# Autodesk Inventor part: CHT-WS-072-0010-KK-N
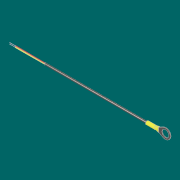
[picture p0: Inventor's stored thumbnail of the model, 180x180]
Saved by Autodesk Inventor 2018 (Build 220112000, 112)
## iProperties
Created: 2017-05
Part Number: CHT-WS-072-0010-KK-N
Material: Generic
Document SubType Name: Modeling
Designer: JN
Density: 1 g/cm^3
Appearance: Steel - Polished
Author: JN
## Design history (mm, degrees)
sketch "Sketch1"
  geometry: L1 (-3.534, 6.574)-(-10.033, 3.097); L2 (-10.033, 3.097)-(-10.033, -3.161); L3 (-10.033, -3.161)-(-3.425, -6.697); L4 (-10.033, -0.032)-(7.494, -0.032); L5 (0.001, 7.461)-(0.001, -7.525); C1 r 5.258 at (0.001, -0.032); A1 r 7.493 centre (0.001, -0.032) between (-3.534, -6.639) and (-3.534, 6.574)
  constraints: 10 end point, 5 point on circle, 2 centre point, 2 tangent, 2 vertical, 1 coincident, 1 midpoint, 1 point on line, 1 other
  dimensions: "d0" = 10.5156 diameter of C1; "d1" = 14.986 diameter of A1
extrude "Extrusion1" new body sketch "Sketch1" stored distance "d7" = 1.0668; taper "d8" = 0 deg
sketch "Sketch3"
  geometry: L1 (-1.067, 0)-(0, 0) reference; L2 (0, 6.258)-(0, 0) reference; L3 (-1.067, 6.258)-(0, 6.258) reference; L4 (-1.067, 0)-(-1.067, 6.258) reference; L5 (0.317, 6.575)-(-1.702, 6.575); L6 (-1.702, 6.575)-(-1.702, -0.318); L7 (-1.702, -0.318)-(0.317, -0.318); L8 (0.317, -0.318)-(0.317, 6.575); L9 (-0.692, 6.575)-(-0.692, -0.318); L10 (0.318, 3.129)-(-1.702, 3.129); 1 further point
  constraints: 12 end point, 6 parallel, 5 midpoint, 1 horizontal, 1 perpendicular
  dimensions: "d15" = 0.3175 distance between parallel lines of L2 L8; "d16" = 0.635 distance between parallel lines of L4 L6; "d17" = 0.3175 distance between parallel lines of L3 L5; "d18" = 0.3175 distance between parallel lines of L1 L7
  node "Projected Loop1"
workplane "Work Plane1"
sketch "Sketch4"
  geometry: L1 (0.317, -0.318)-(0.317, 6.575) reference; L2 (0.317, 6.575)-(-1.702, 6.575) reference; L3 (-1.702, 6.575)-(-1.702, -0.318) reference; L4 (-1.702, -0.318)-(0.317, -0.318) reference; L5 (0.317, 3.129)-(-1.702, 3.129); L6 (-0.692, 6.575)-(-0.692, -0.318); L7 (-2.337, 5.064)-(-2.337, 1.193); A1 r 2.54 centre (-0.692, 3.129) between (-2.337, 1.193) and (-2.337, 5.064); 2 further points
  constraints: 6 end point, 5 midpoint, 2 point on circle, 1 centre point, 1 coincident, 1 point on line, 1 vertical
  dimensions: "d37" = 5.08 diameter of A1; "d38" = 0.635 distance between parallel lines of L3 L7
sketch "3D Sketch1"
loft "Loft1" sketch "Sketch4", "3D Sketch1" dims "d21" = 0, "d22" = 90 deg, "d25" = 0, "d26" = 90 deg, "d39" = 0, "d40" = 90 deg
sketch "Sketch5"
  geometry: L1 (-0.635, 5.382)-(-0.635, 1.511) reference; A1 r 2.54 centre (1.01, 3.446) between (1.221, 0.915) and (1.928, 5.814) reference; A2 r 2.54 centre (1.01, 3.446) between (1.928, 5.814) and (-0.635, 5.382) reference; A3 r 2.54 centre (1.01, 3.446) between (1.928, 5.814) and (-0.635, 5.382) reference; A4 r 2.54 centre (1.01, 3.446) between (-0.635, 1.511) and (1.221, 0.915) reference; A5 r 2.54 centre (1.01, 3.446) between (1.221, 0.915) and (1.928, 5.814) reference
extrude "Extrusion3" new body sketch "Sketch5" distance "d27" = 12.7; taper "d28" = 0 deg
sketch "Sketch6" dims "d29" = 1.27, "d30" = 1.778
  geometry: L1 (2.019, 0)-(2.019, 6.893) reference; L2 (0, 6.893)-(0, 0) reference; L3 (2.019, 6.893)-(0, 6.893) reference; L4 (0, 0)-(2.019, 0) reference; L5 (2.019, 0)-(2.019, 6.893) reference; L6 (2.019, 6.893)-(0, 6.893) reference; L7 (1.01, 6.893)-(1.01, 0); L8 (0, 0)-(2.019, 0) reference; L9 (0, 6.893)-(0, 0) reference; L10 (0, 3.446)-(2.019, 3.446); 2 further points; 1 other entity
  constraints: 5 midpoint, 4 end point, 2 other
  node "Projected Loop4"
extrude "Extrusion4" cut sketch "Sketch6" stored distance "d32" = 12.7; taper "d33" = 0 deg
extrude "Extrusion5" new body sketch "Sketch6" distance "d34" = 152.4; taper "d35" = 0 deg
sketch "Sketch7"
  geometry: L1 (2.28, 3.446)-(-0.26, 3.446) reference; L2 (1.01, 5.224)-(1.01, 1.668) reference; C1 r 0.635 at (1.01, 4.081); C2 r 0.635 at (1.01, 2.811); 1 further point; 1 other entity
  constraints: 4 end point, 2 centre point, 2 horizontal, 2 vertical, 1 point on line, 1 symmetric about line, 1 tangent, 6 other
  dimensions: "d41" = 1.27 diameter of C1
workplane "Work Plane2"
sketch "Sketch8"
  geometry: C1 r 0.635 at (1.01, 4.081) reference; C2 r 0.635 at (1.01, 2.811) reference; C3 r 0.635 at (1.01, 4.399); C4 r 0.635 at (1.01, 2.494)
  constraints: 2 centre point
  dimensions: "d43" = 1.27 diameter of C3; "d45" = 0.3175 distance of C1.centre C3.centre; "d46" = 1.27 diameter of C4; "d47" = 0.3175 distance of C2.centre C4.centre
sketch "3D Sketch2"
loft "Loft2" dims "d48" = 0, "d49" = 90 deg, "d50" = 0, "d51" = 90 deg, "d52" = 0, "d53" = 90 deg
loft "Loft3" dims "d54" = 0, "d55" = 90 deg, "d56" = 0, "d57" = 90 deg, "d58" = 0, "d59" = 90 deg
sketch "Sketch9"
  geometry: C1 r 0.381 at (0, 0)
  constraints: 1 centre point
  dimensions: "d60" = 0.762 diameter of C1
sketch "Sketch10"
  geometry: C1 r 0.381 at (0, 0)
  constraints: 1 centre point
  dimensions: "d61" = 0.762 diameter of C1
extrude "Extrusion6" join sketch "Sketch9" distance "d62" = 8.46667; taper "d63" = 0 deg
extrude "Extrusion7" join sketch "Sketch10" distance "d64" = 8.46667; taper "d65" = 0 deg
body "Solid1"
body "Solid2"
body "Solid3"
body "Solid4"
node "Projected Loop5"
other parameters: "d3" = 14.986 (derived), "d5" = 10.49782 (derived), "d19" = 5.08, "d42" = 44.45
